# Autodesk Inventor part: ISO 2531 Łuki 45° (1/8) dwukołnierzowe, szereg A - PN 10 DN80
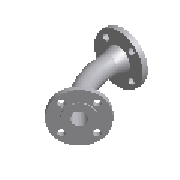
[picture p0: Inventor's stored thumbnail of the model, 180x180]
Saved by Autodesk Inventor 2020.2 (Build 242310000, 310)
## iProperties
Manager: www.cadconsulting.pl
Company: Fabian Stasiak CAD Consulting
IsCustomPart: 0
NAME: PIPING: ISO 2531 45 Deg Double Flanged Bend - PN 10
DATA: <meta><inlinegroups number="0" deflen="0"></inlinegroups><connections number="2"></connections><angles><a>2.35619449019234</a></angles></meta>
Created: 2014-02
Part Number: ISO 2531 Łuki 45° (1/8) dwukołnierzowe, szereg A - PN 10 DN80
Material: Żeliwo sferoidalne
Description: Rury, łączniki, akcesoria z żeliwa sferoidalnego i ich złącza do zastosowań w instalacjach wodnych lub gazowych - Łuki 45°(1/8) dwukołnierzowe, szereg A - PN 10
Document SubType Name: Modeling
Standard: ISO 2531
Designer: F.Stasiak
Standard Revision: Fifth edition  1998-08-15
Standards Organization: ISO
Language: pl-PL
Size Designation: DN80
Categories: <MemberInstance><Categories><Category DisplayName="Rury cienko- i grubościenne" InternalName="4347fa0f-2144-441d-94cd-e3e15c92b736" Mnemonic="TUBEANDPIPE"><Cate
Density: 7.15 g/cm^3
Appearance: Ciemnoszary
Catalog Web Link: www.expertbooks.pl
Author: F.Stasiak
Subject: Zbiór ćwiczeń. Autodesk Inventor 2020. Kurs Professional
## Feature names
1. Revolution1
2. Sweep1
3. Revolution2
4. Extrusion1
5. Circular Pattern1
6. Extrusion2
7. Circular Pattern2
## Parameters: L2 = 19 mm, f1 = 3 mm, d11 = 132 mm, e = 7 mm, C7 = 19 mm, d2 = 7 mm, d3 = 132 mm, d4 = 3 mm, d5 = 15 deg, d7 = 66.66667 mm, d15 = 90 deg, d9 = 7 mm, d10 = 3 mm, d13 = 132 mm, d17 = 66.66667 mm, d18 = 7 mm, d19 = 0, d27 = 90 deg, d21 = 16 mm, d22 = 0, d24 = 360 deg, d26 = 16 mm, d28 = 0, d30 = 360 deg, d31 = 19 mm, d32 = 19 mm, d34 = 135 deg, d36 = 15 deg, d37 = 19 mm, d38 = 22.5 deg, d39 = 19 mm, d41 = 22.5 deg, d51 = 0, Size_Designation = 12.345 mm
